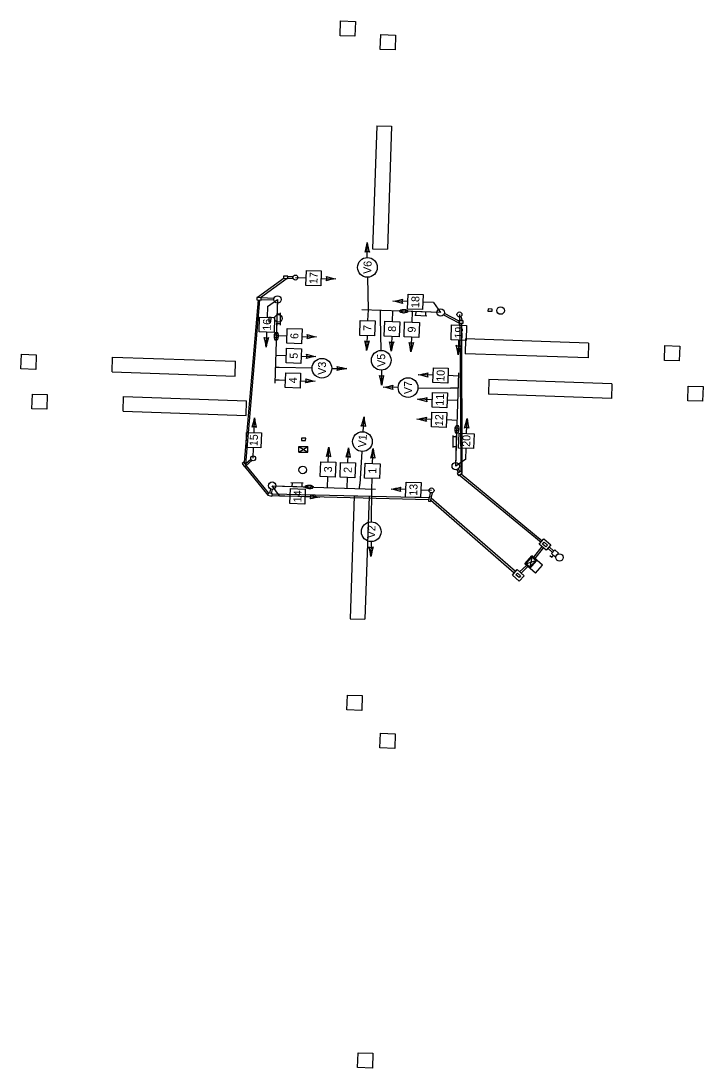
# Model space of a CAD drawing. Extents: x 981632 to 1295361, y 220574 to 1844132.
# Drawn here: x 992357 to 992633.9, y 1843107.7 to 1843532.8 of the extents above; entities that cross this region are included whole.
import ezdxf

# ---------------------------------------------------------------- set-up
doc = ezdxf.new("R2010")
doc.units = 0
for name, color, linetype in [('No Plot', 7, 'Continuous'), ('R_Existing Signal', 7, 'Continuous'), ('T_Drafting', 7, 'Continuous'), ('T_Indications', 7, 'Continuous'), ('V-SIGNAL-CONDUIT', 7, 'Continuous'), ('V-SIGNAL-HEAD', 7, 'Continuous'), ('V-SIGNAL-HEAD-MOT', 7, 'Continuous'), ('V-SIGNAL-LOOP', 7, 'Continuous'), ('V-SIGNAL-MAST', 7, 'Continuous'), ('V-SIGNAL-POLE', 7, 'Continuous')]:
    doc.layers.add(name, color=color, linetype=linetype)

msp = doc.modelspace()

# ---------------------------------------------------------------- linework, layer by layer
at = {"layer": 'No Plot'}
msp.add_line((992460.31, 1843387.1), (992461.89, 1843387.05), dxfattribs=at)
at = {"layer": 'R_Existing Signal'}
for p, q in [((992546.62, 1843415.9), (992546.58, 1843414.99)), ((992546.58, 1843414.99), (992548.33, 1843414.93)), ((992548.37, 1843415.84), (992546.62, 1843415.9)), ((992548.33, 1843414.93), (992548.37, 1843415.84)), ((992457.65, 1843412.39), (992457.6, 1843410.64)), ((992457.6, 1843410.64), (992458.51, 1843410.61)), ((992458.57, 1843412.36), (992457.65, 1843412.39)), ((992458.51, 1843410.61), (992458.57, 1843412.36)), ((992470.87, 1843363.44), (992470.84, 1843362.53)), ((992472.62, 1843363.38), (992470.87, 1843363.44)), ((992472.59, 1843362.47), (992472.62, 1843363.38)), ((992469.87, 1843360.05), (992473.53, 1843357.8)), ((992469.87, 1843357.8), (992473.53, 1843360.05)), ((992469.87, 1843360.05), (992473.53, 1843360.05)), ((992469.87, 1843357.8), (992469.87, 1843360.05)), ((992470.84, 1843362.53), (992472.59, 1843362.47)), ((992473.53, 1843357.8), (992473.53, 1843360.05)), ((992469.87, 1843357.8), (992473.53, 1843357.8))]:
    msp.add_line(p, q, dxfattribs=at)
for centre in [(992551.74, 1843415.25), (992461.54, 1843412.06), (992471.4, 1843350.52)]:
    msp.add_circle(centre, 1.53, dxfattribs=at)
at = {"layer": 'T_Drafting'}
for p, q in [((992573.69, 1843318.06), (992572.37, 1843316.56)), ((992572.37, 1843316.56), (992573.88, 1843315.24)), ((992573.69, 1843318.06), (992575.2, 1843316.75)), ((992575.2, 1843316.75), (992573.88, 1843315.24)), ((992561.56, 1843312.36), (992564.41, 1843315.62)), ((992565.88, 1843308.58), (992561.56, 1843312.36)), ((992562.02, 1843312.39), (992564.44, 1843315.15)), ((992563.59, 1843311.02), (992562.02, 1843312.39)), ((992562.04, 1843312.41), (992566, 1843313.78)), ((992564.44, 1843315.15), (992563.59, 1843311.02)), ((992563.59, 1843311.02), (992566, 1843313.78)), ((992563.62, 1843310.56), (992566.47, 1843313.82)), ((992568.73, 1843311.84), (992564.41, 1843315.62)), ((992566, 1843313.78), (992564.44, 1843315.15)), ((992571.72, 1843315.8), (992572.47, 1843315.15)), ((992573.13, 1843315.9), (992572.47, 1843315.15)), ((992565.88, 1843308.58), (992568.73, 1843311.84))]:
    msp.add_line(p, q, dxfattribs=at)
msp.add_circle((992575.67, 1843315.01), 1.5, dxfattribs=at)
at = {"layer": 'T_Indications'}
for p, q in [((992497.62, 1843436.78), (992497.54, 1843442.84)), ((992468.42, 1843428.65), (992472.77, 1843428.5)), ((992478.83, 1843428.31), (992484.87, 1843428.09)), ((992514.08, 1843418.89), (992508.04, 1843419.09)), ((992524.49, 1843418.53), (992520.14, 1843418.68)), ((992457.09, 1843416.84), (992456.94, 1843412.5)), ((992497.91, 1843415.48), (992497.76, 1843411.14)), ((992507.91, 1843415.14), (992507.75, 1843410.79)), ((992515.9, 1843414.86), (992515.75, 1843410.52)), ((992535.03, 1843413.66), (992534.88, 1843409.32)), ((992456.74, 1843406.44), (992456.53, 1843400.4)), ((992460.67, 1843405.1), (992465.02, 1843404.96)), ((992471.01, 1843404.76), (992477.05, 1843404.56)), ((992497.57, 1843405.07), (992497.35, 1843399.04)), ((992507.56, 1843404.73), (992507.35, 1843398.7)), ((992515.56, 1843404.46), (992515.34, 1843398.42)), ((992534.69, 1843403.26), (992534.47, 1843397.22)), ((992460.41, 1843397.11), (992464.75, 1843396.96)), ((992470.75, 1843396.77), (992476.79, 1843396.57)), ((992483.19, 1843391.76), (992489.26, 1843391.67)), ((992503.35, 1843391.05), (992503.45, 1843384.99)), ((992524.37, 1843389), (992518.34, 1843389.2)), ((992534.71, 1843388.66), (992530.37, 1843388.81)), ((992460.08, 1843387.11), (992464.43, 1843386.97)), ((992470.42, 1843386.77), (992476.46, 1843386.57)), ((992510.16, 1843384.04), (992504.1, 1843384.14)), ((992524.04, 1843379.01), (992518.01, 1843379.21)), ((992534.39, 1843378.67), (992530.04, 1843378.81)), ((992451.62, 1843365.65), (992451.84, 1843371.69)), ((992495.9, 1843366.02), (992496.29, 1843372.08)), ((992523.78, 1843371.01), (992517.74, 1843371.21)), ((992534.12, 1843370.67), (992529.78, 1843370.82)), ((992537.91, 1843365.36), (992538.11, 1843371.4)), ((992451.27, 1843355.25), (992451.43, 1843359.59)), ((992481.78, 1843353.78), (992481.99, 1843359.81)), ((992489.77, 1843353.5), (992489.99, 1843359.54)), ((992499.77, 1843353.16), (992499.98, 1843359.2)), ((992537.57, 1843354.95), (992537.72, 1843359.3)), ((992481.43, 1843343.37), (992481.59, 1843347.72)), ((992489.43, 1843343.1), (992489.58, 1843347.44)), ((992499.42, 1843342.76), (992499.58, 1843347.1)), ((992513.3, 1843342.55), (992507.27, 1843342.77)), ((992523.71, 1843342.2), (992519.36, 1843342.36)), ((992461.92, 1843340.08), (992466.27, 1843339.91)), ((992472.33, 1843339.7), (992478.36, 1843339.47)), ((992499.17, 1843321.45), (992499.1, 1843315.39))]:
    msp.add_line(p, q, dxfattribs=at)
for points in [[(992472.66, 1843425.48), (992472.88, 1843431.54), (992478.94, 1843431.33), (992478.72, 1843425.27)], [(992520.24, 1843421.71), (992520.04, 1843415.65), (992513.98, 1843415.85), (992514.18, 1843421.92)], [(992453.92, 1843412.6), (992459.98, 1843412.39), (992459.77, 1843406.33), (992453.71, 1843406.55)], [(992494.74, 1843411.24), (992500.81, 1843411.03), (992500.59, 1843404.97), (992494.53, 1843405.18)], [(992504.74, 1843410.9), (992510.8, 1843410.68), (992510.58, 1843404.63), (992504.52, 1843404.84)], [(992512.73, 1843410.62), (992518.79, 1843410.41), (992518.58, 1843404.35), (992512.52, 1843404.57)], [(992464.92, 1843401.96), (992465.11, 1843407.96), (992471.11, 1843407.76), (992470.91, 1843401.76)], [(992531.86, 1843409.43), (992537.92, 1843409.21), (992537.71, 1843403.15), (992531.65, 1843403.37)], [(992464.66, 1843393.97), (992464.85, 1843399.96), (992470.85, 1843399.76), (992470.65, 1843393.77)], [(992464.33, 1843383.97), (992464.52, 1843389.97), (992470.52, 1843389.77), (992470.32, 1843383.77)], [(992530.47, 1843391.8), (992530.27, 1843385.81), (992524.27, 1843386), (992524.47, 1843392)], [(992530.14, 1843381.81), (992529.94, 1843375.81), (992523.95, 1843376.01), (992524.14, 1843382.01)], [(992529.88, 1843373.81), (992529.68, 1843367.82), (992523.68, 1843368.01), (992523.88, 1843374.01)], [(992454.44, 1843359.48), (992448.38, 1843359.7), (992448.6, 1843365.76), (992454.66, 1843365.54)], [(992540.74, 1843359.19), (992534.68, 1843359.4), (992534.88, 1843365.46), (992540.94, 1843365.25)], [(992484.6, 1843347.61), (992478.54, 1843347.82), (992478.75, 1843353.88), (992484.82, 1843353.67)], [(992492.6, 1843347.34), (992486.54, 1843347.55), (992486.75, 1843353.61), (992492.81, 1843353.4)], [(992502.59, 1843346.99), (992496.53, 1843347.21), (992496.74, 1843353.27), (992502.8, 1843353.05)], [(992466.15, 1843336.9), (992466.38, 1843342.96), (992472.44, 1843342.72), (992472.21, 1843336.66)], [(992519.47, 1843345.37), (992519.25, 1843339.31), (992513.19, 1843339.53), (992513.41, 1843345.59)]]:
    msp.add_lwpolyline(points, close=True, dxfattribs=at)
for centre in [(992497.68, 1843432.78), (992503.28, 1843395.05), (992479.19, 1843391.82), (992514.16, 1843383.98), (992495.64, 1843362.03), (992499.22, 1843325.45)]:
    msp.add_circle(centre, 4, dxfattribs=at)
for centre, radius, start, end in [((992468.34, 1843446.85), 29.47, 344.4414, 352.1795), ((992526.61, 1843447.66), 29.47, 189.3961, 197.1342), ((992497.61, 1843437.58), 1.63, 58.9405, 122.6351), ((992479.6, 1843428.28), 1.63, 326.1248, 29.8195), ((992488.24, 1843398.81), 29.47, 96.5805, 104.3186), ((992490.31, 1843457.06), 29.47, 251.6257, 259.3638), ((992504.62, 1843448.36), 29.47, 276.6738, 284.4119), ((992502.65, 1843390.11), 29.47, 71.719, 79.4571), ((992513.31, 1843418.91), 1.63, 146.2181, 209.9128), ((992456.72, 1843405.66), 1.63, 236.1145, 299.8091), ((992427.25, 1843397.03), 29.47, 6.5701, 14.3082), ((992485.49, 1843394.96), 29.47, 161.6154, 169.3535), ((992471.79, 1843404.74), 1.63, 326.2721, 29.9668), ((992480.5, 1843375.29), 29.47, 96.7278, 104.4659), ((992482.42, 1843433.54), 29.47, 251.773, 259.5111), ((992497.54, 1843404.3), 1.63, 236.1248, 299.8195), ((992468.08, 1843395.66), 29.47, 6.5805, 14.3186), ((992526.32, 1843393.6), 29.47, 161.6257, 169.3638), ((992507.53, 1843403.96), 1.63, 236.1248, 299.8195), ((992478.07, 1843395.32), 29.47, 6.5805, 14.3186), ((992536.31, 1843393.26), 29.47, 161.6257, 169.3638), ((992515.53, 1843403.68), 1.63, 236.1248, 299.8195), ((992486.07, 1843395.04), 29.47, 6.5805, 14.3186), ((992544.31, 1843392.98), 29.47, 161.6257, 169.3638), ((992471.52, 1843396.74), 1.63, 326.2721, 29.9668), ((992482.15, 1843425.55), 29.47, 251.773, 259.5111), ((992534.66, 1843402.49), 1.63, 236.1248, 299.8195), ((992505.19, 1843393.85), 29.47, 6.5805, 14.3186), ((992563.44, 1843391.78), 29.47, 161.6257, 169.3638), ((992480.24, 1843367.3), 29.47, 96.7278, 104.4659), ((992483.99, 1843391.75), 1.63, 327.2794, 30.974), ((992493.22, 1843362.46), 29.47, 97.735, 105.4731), ((992494.11, 1843420.74), 29.47, 252.7802, 260.5184), ((992503.36, 1843390.25), 1.63, 239.1324, 302.8271), ((992474.39, 1843380.08), 29.47, 9.5881, 17.3262), ((992532.66, 1843381.07), 29.47, 164.6333, 172.3714), ((992514.88, 1843418.47), 29.47, 276.7278, 284.4659), ((992512.97, 1843360.22), 29.47, 71.773, 79.5111), ((992523.6, 1843389.03), 1.63, 146.2721, 209.9668), ((992471.2, 1843386.75), 1.63, 326.2721, 29.9668), ((992479.91, 1843357.3), 29.47, 96.7278, 104.4659), ((992481.82, 1843415.55), 29.47, 251.773, 259.5111), ((992500.14, 1843413.34), 29.47, 277.719, 285.4571), ((992509.36, 1843384.06), 1.63, 147.2633, 210.958), ((992499.23, 1843355.07), 29.47, 72.7642, 80.5023), ((992514.55, 1843408.48), 29.47, 276.7278, 284.4659), ((992512.64, 1843350.23), 29.47, 71.773, 79.5111), ((992523.27, 1843379.03), 1.63, 146.2721, 209.9668), ((992422.88, 1843377.15), 29.47, 341.5803, 349.3184), ((992481.12, 1843375.04), 29.47, 186.5351, 194.2732), ((992467.5, 1843378.36), 29.47, 339.9576, 347.6957), ((992525.66, 1843374.6), 29.47, 184.9124, 192.6505), ((992514.29, 1843400.48), 29.47, 276.7278, 284.4659), ((992523.01, 1843371.04), 1.63, 146.2721, 209.9668), ((992451.65, 1843366.43), 1.63, 56.0794, 119.7741), ((992495.95, 1843366.82), 1.63, 54.4567, 118.1514), ((992512.38, 1843342.23), 29.47, 71.773, 79.5111), ((992509.14, 1843376.8), 29.47, 341.6897, 349.4278), ((992537.93, 1843366.13), 1.63, 56.1888, 119.8834), ((992567.39, 1843374.81), 29.47, 186.6444, 194.3825), ((992453.03, 1843365.25), 29.47, 341.6248, 349.3629), ((992511.27, 1843363.19), 29.47, 186.5795, 194.3176), ((992461.02, 1843364.98), 29.47, 341.6248, 349.3629), ((992519.26, 1843362.92), 29.47, 186.5795, 194.3176), ((992471.02, 1843364.64), 29.47, 341.6248, 349.3629), ((992529.26, 1843362.57), 29.47, 186.5795, 194.3176), ((992481.81, 1843354.55), 1.63, 56.1239, 119.8185), ((992489.8, 1843354.28), 1.63, 56.1239, 119.8185), ((992499.79, 1843353.93), 1.63, 56.1239, 119.8185), ((992503.91, 1843372.05), 29.47, 276.5351, 284.2732), ((992501.8, 1843313.81), 29.47, 71.5803, 79.3184), ((992512.53, 1843342.58), 1.63, 146.0794, 209.7741), ((992473.1, 1843339.67), 1.63, 325.9651, 29.6598), ((992481.66, 1843310.18), 29.47, 96.4208, 104.1589), ((992483.88, 1843368.42), 29.47, 251.466, 259.2041), ((992469.91, 1843311.32), 29.47, 7.9412, 15.6793), ((992499.16, 1843320.66), 1.63, 237.4856, 301.1802), ((992528.19, 1843310.64), 29.47, 162.9865, 170.7246)]:
    msp.add_arc(centre, radius, start, end, dxfattribs=at)
at = {"layer": 'V-SIGNAL-CONDUIT'}
for p, q in [((992463.82, 1843428.35), (992453.05, 1843420.5)), ((992465.02, 1843428.31), (992454.25, 1843420.46)), ((992463.58, 1843429.27), (992463.55, 1843428.36)), ((992463.55, 1843428.36), (992465.3, 1843428.3)), ((992465.33, 1843429.21), (992463.58, 1843429.27)), ((992465.3, 1843428.3), (992465.33, 1843429.21)), ((992465.3, 1843428.38), (992467.48, 1843428.31)), ((992465.33, 1843429.12), (992467.51, 1843429.05)), ((992453.32, 1843419.57), (992447.58, 1843353.66)), ((992453.92, 1843419.55), (992448.11, 1843352.9)), ((992452.77, 1843420.51), (992452.74, 1843419.59)), ((992452.74, 1843419.59), (992454.49, 1843419.53)), ((992454.52, 1843420.45), (992452.77, 1843420.51)), ((992454.49, 1843419.53), (992454.52, 1843420.45)), ((992459.69, 1843419.44), (992454.49, 1843419.62)), ((992459.71, 1843420.18), (992454.52, 1843420.36)), ((992528.86, 1843414.13), (992534.82, 1843411.04)), ((992528.52, 1843413.47), (992534.79, 1843410.22)), ((992534.82, 1843411.09), (992534.79, 1843410.17)), ((992534.79, 1843410.17), (992536.54, 1843410.11)), ((992536.57, 1843411.03), (992534.82, 1843411.09)), ((992534.9, 1843412.67), (992535.31, 1843411.07)), ((992535.66, 1843349.97), (992535.29, 1843410.16)), ((992535.62, 1843412.85), (992536.08, 1843411.05)), ((992536.11, 1843349.17), (992536.03, 1843410.13)), ((992536.54, 1843410.11), (992536.57, 1843411.03)), ((992450.36, 1843354.83), (992448.15, 1843352.84)), ((992447.55, 1843353.7), (992446.8, 1843353.18)), ((992446.8, 1843353.18), (992447.8, 1843351.74)), ((992448.55, 1843352.27), (992447.55, 1843353.7)), ((992447.8, 1843351.74), (992448.55, 1843352.27)), ((992447.87, 1843351.79), (992457.17, 1843340.31)), ((992448.48, 1843352.22), (992457.39, 1843341.2)), ((992450.76, 1843354.38), (992448.5, 1843352.35)), ((992533.9, 1843350.59), (992534.58, 1843349.37)), ((992534.54, 1843350.95), (992535.22, 1843349.73)), ((992535.66, 1843349.97), (992534.13, 1843349.12)), ((992534.13, 1843349.12), (992534.58, 1843348.32)), ((992534.58, 1843348.32), (992536.11, 1843349.17)), ((992534.98, 1843348.54), (992568.14, 1843321.21)), ((992536.11, 1843349.17), (992535.66, 1843349.97)), ((992535.68, 1843348.93), (992568.63, 1843321.77)), ((992458.31, 1843342.82), (992457.88, 1843341.08)), ((992459.03, 1843342.64), (992458.6, 1843340.91)), ((992457.39, 1843341.2), (992457.17, 1843340.31)), ((992457.17, 1843340.31), (992458.87, 1843339.89)), ((992459.09, 1843340.78), (992457.39, 1843341.2)), ((992458.87, 1843339.89), (992459.09, 1843340.78)), ((992522.53, 1843338.44), (992458.89, 1843339.97)), ((992522.67, 1843339.17), (992459.07, 1843340.71)), ((992522.75, 1843339.6), (992522.42, 1843337.88)), ((992522.42, 1843337.88), (992523.32, 1843337.71)), ((992523.65, 1843339.43), (992522.75, 1843339.6)), ((992523.17, 1843341.36), (992522.83, 1843339.58)), ((992523.32, 1843337.71), (992523.65, 1843339.43)), ((992557.23, 1843308.68), (992523.41, 1843338.18)), ((992523.9, 1843341.22), (992523.56, 1843339.44)), ((992557.72, 1843309.23), (992523.57, 1843339.02)), ((992567.4, 1843320.36), (992569.32, 1843322.55)), ((992568.81, 1843320.45), (992569.41, 1843321.14)), ((992569.32, 1843322.55), (992572.14, 1843320.08)), ((992569.41, 1843321.14), (992570.73, 1843319.99)), ((992568.51, 1843319.38), (992565.03, 1843315.07)), ((992569.07, 1843318.89), (992565.59, 1843314.59)), ((992570.22, 1843317.89), (992567.4, 1843320.36)), ((992570.12, 1843319.3), (992568.81, 1843320.45)), ((992570.73, 1843319.99), (992570.12, 1843319.3)), ((992572.14, 1843320.08), (992570.22, 1843317.89)), ((992572.8, 1843317.05), (992570.94, 1843318.71)), ((992573.29, 1843317.6), (992571.42, 1843319.27)), ((992556.51, 1843307.85), (992558.43, 1843310.05)), ((992559.34, 1843305.38), (992556.51, 1843307.85)), ((992557.92, 1843307.95), (992558.53, 1843308.64)), ((992559.24, 1843306.79), (992557.92, 1843307.95)), ((992558.43, 1843310.05), (992561.26, 1843307.58)), ((992558.53, 1843308.64), (992559.84, 1843307.48)), ((992562.22, 1843311.78), (992559.46, 1843309.15)), ((992562.78, 1843311.29), (992560.02, 1843308.66)), ((992559.84, 1843307.48), (992559.24, 1843306.79)), ((992561.26, 1843307.58), (992559.34, 1843305.38))]:
    msp.add_line(p, q, dxfattribs=at)
at = {"layer": 'V-SIGNAL-HEAD'}
for p, q in [((992461.15, 1843419.76), (992460.66, 1843404.77)), ((992527.4, 1843414.47), (992512.41, 1843414.98)), ((992533.51, 1843352.04), (992534, 1843367.02)), ((992459.01, 1843344.14), (992474, 1843343.63))]:
    msp.add_line(p, q, dxfattribs=at)
for centre in [(992512.41, 1843414.98), (992460.66, 1843404.77), (992534.01, 1843367.02), (992474, 1843343.63)]:
    msp.add_circle(centre, 0.75, dxfattribs=at)
for centre, major_axis in [((992512.41, 1843414.98), (1.7, -0.06)), ((992460.66, 1843404.77), (0.06, 1.7)), ((992534.01, 1843367.02), (-0.06, -1.7)), ((992474, 1843343.63), (-1.7, 0.06))]:
    msp.add_ellipse(centre, major_axis=major_axis, ratio=0.441176, dxfattribs=at)
at = {"layer": 'V-SIGNAL-LOOP'}
for p, q in [((992486.59, 1843526.84), (992486.8, 1843532.84)), ((992486.8, 1843532.84), (992492.79, 1843532.63)), ((992492.79, 1843532.63), (992492.59, 1843526.64)), ((992492.59, 1843526.64), (992486.59, 1843526.84)), ((992502.88, 1843521.28), (992503.09, 1843527.28)), ((992503.09, 1843527.28), (992509.09, 1843527.07)), ((992509.09, 1843527.07), (992508.88, 1843521.07)), ((992508.88, 1843521.07), (992502.88, 1843521.28)), ((992501.48, 1843490.31), (992499.77, 1843440.34)), ((992501.48, 1843490.31), (992507.48, 1843490.1)), ((992507.48, 1843490.1), (992505.76, 1843440.13)), ((992499.77, 1843440.34), (992505.76, 1843440.13)), ((992537.51, 1843403.74), (992537.3, 1843397.74)), ((992587.48, 1843402.03), (992537.51, 1843403.74)), ((992587.48, 1843402.03), (992587.28, 1843396.03)), ((992357, 1843391.53), (992357.21, 1843397.53)), ((992357.21, 1843397.53), (992363.21, 1843397.32)), ((992363.21, 1843397.32), (992363, 1843391.33)), ((992587.28, 1843396.03), (992537.3, 1843397.74)), ((992618.26, 1843395), (992618.46, 1843401)), ((992618.46, 1843401), (992624.46, 1843400.79)), ((992624.46, 1843400.79), (992624.25, 1843394.79)), ((992393.99, 1843390.36), (992394.19, 1843396.36)), ((992394.19, 1843396.36), (992444.16, 1843394.64)), ((992443.96, 1843388.65), (992444.16, 1843394.64)), ((992624.25, 1843394.79), (992618.26, 1843395)), ((992363, 1843391.33), (992357, 1843391.53)), ((992393.99, 1843390.36), (992443.96, 1843388.65)), ((992546.97, 1843387.25), (992546.77, 1843381.25)), ((992596.94, 1843385.53), (992546.97, 1843387.25)), ((992596.94, 1843385.53), (992596.74, 1843379.54)), ((992627.73, 1843378.6), (992627.93, 1843384.6)), ((992627.93, 1843384.6), (992633.93, 1843384.39)), ((992633.93, 1843384.39), (992633.72, 1843378.39)), ((992361.47, 1843375.34), (992361.68, 1843381.34)), ((992361.68, 1843381.34), (992367.68, 1843381.13)), ((992367.68, 1843381.13), (992367.47, 1843375.14)), ((992398.46, 1843374.34), (992398.67, 1843380.33)), ((992398.67, 1843380.33), (992448.64, 1843378.62)), ((992596.74, 1843379.54), (992546.77, 1843381.25)), ((992448.43, 1843372.62), (992448.64, 1843378.62)), ((992633.72, 1843378.39), (992627.73, 1843378.6)), ((992367.47, 1843375.14), (992361.47, 1843375.34)), ((992398.46, 1843374.34), (992448.43, 1843372.62)), ((992492.33, 1843340.06), (992490.61, 1843290.09)), ((992492.33, 1843340.06), (992498.32, 1843339.86)), ((992498.32, 1843339.86), (992496.61, 1843289.89)), ((992490.61, 1843290.09), (992496.61, 1843289.89)), ((992489.34, 1843253.11), (992489.55, 1843259.11)), ((992489.55, 1843259.11), (992495.55, 1843258.9)), ((992495.55, 1843258.9), (992495.34, 1843252.91)), ((992495.34, 1843252.91), (992489.34, 1843253.11)), ((992502.77, 1843237.64), (992502.97, 1843243.64)), ((992502.97, 1843243.64), (992508.97, 1843243.44)), ((992508.97, 1843243.44), (992508.76, 1843237.44)), ((992508.76, 1843237.44), (992502.77, 1843237.64)), ((992493.69, 1843107.88), (992493.89, 1843113.88)), ((992493.89, 1843113.88), (992499.89, 1843113.67)), ((992499.89, 1843113.67), (992499.68, 1843107.67)), ((992499.68, 1843107.67), (992493.69, 1843107.88))]:
    msp.add_line(p, q, dxfattribs=at)
at = {"layer": 'V-SIGNAL-MAST'}
for p, q in [((992462.34, 1843409.33), (992462.42, 1843414.32)), ((992517.35, 1843413.34), (992517.41, 1843414.8)), ((992521.35, 1843413.18), (992521.41, 1843414.63)), ((992462.35, 1843409.83), (992460.89, 1843409.85)), ((992462.41, 1843413.82), (992460.96, 1843413.85)), ((992516.85, 1843413.37), (992521.85, 1843413.15)), ((992532.4, 1843364.58), (992532.31, 1843359.58)), ((992532.39, 1843364.08), (992533.84, 1843364.06)), ((992532.32, 1843360.08), (992533.77, 1843360.06)), ((992471.58, 1843345.16), (992466.58, 1843345.33)), ((992467.08, 1843345.32), (992467.03, 1843343.87)), ((992471.08, 1843345.18), (992471.03, 1843343.73))]:
    msp.add_line(p, q, dxfattribs=at)
at = {"layer": 'V-SIGNAL-POLE'}
for p, q in [((992497.73, 1843428.78), (992497.91, 1843415.48)), ((992457.09, 1843416.84), (992461.15, 1843419.76)), ((992461.15, 1843419.76), (992460.04, 1843385.78)), ((992524.49, 1843418.53), (992527.4, 1843414.47)), ((992527.4, 1843414.47), (992495.41, 1843415.56)), ((992502.98, 1843412.35), (992502.93, 1843415.31)), ((992503.21, 1843399.05), (992502.98, 1843412.35)), ((992461.89, 1843392.09), (992460.24, 1843392.11)), ((992475.19, 1843391.88), (992461.89, 1843392.09)), ((992533.51, 1843352.04), (992534.76, 1843390.02)), ((992518.16, 1843383.92), (992531.46, 1843383.71)), ((992534.55, 1843383.67), (992531.46, 1843383.71)), ((992495.38, 1843358.04), (992494.53, 1843344.77)), ((992537.57, 1843354.95), (992533.51, 1843352.04)), ((992459.01, 1843344.14), (992500.99, 1843342.7)), ((992461.92, 1843340.08), (992459.01, 1843344.14)), ((992494.41, 1843342.93), (992494.53, 1843344.77)), ((992499.27, 1843329.45), (992499.42, 1843342.76))]:
    msp.add_line(p, q, dxfattribs=at)
for centre, radius in [((992468.42, 1843428.65), 1), ((992461.15, 1843419.76), 1.5), ((992527.4, 1843414.47), 1.5), ((992535.03, 1843413.66), 1), ((992451.27, 1843355.24), 1), ((992533.51, 1843352.04), 1.5), ((992459.01, 1843344.14), 1.5), ((992523.71, 1843342.2), 1)]:
    msp.add_circle(centre, radius, dxfattribs=at)

# ---------------------------------------------------------------- texts
at = {"layer": 'V-SIGNAL-HEAD-MOT'}
for s, rotation, p in [('V6', 87.5733, (992499.19, 1843430.04)), ('17', 88.0361, (992477.34, 1843425.93)), ('18', 88.0361, (992518.65, 1843416.25)), ('16', 88.0361, (992458.39, 1843406.99)), ('6', 88.0361, (992469.6, 1843403.65)), ('7', 88.0361, (992499.25, 1843406.89)), ('8', 88.0361, (992509.25, 1843406.55)), ('9', 88.0361, (992517.24, 1843406.27)), ('19', 88.0361, (992536.33, 1843403.81)), ('5', 88.0361, (992469.34, 1843395.64)), ('V5', 90.9969, (992504.95, 1843392.39)), ('V3', 89.1494, (992480.78, 1843389.13)), ('10', 88.0361, (992528.91, 1843386.27)), ('4', 88.0361, (992469.01, 1843385.66)), ('V7', 89.1091, (992515.74, 1843381.28)), ('11', 88.0361, (992528.59, 1843376.58)), ('12', 88.0361, (992528.32, 1843368.26)), ('15', 88.0361, (992453.06, 1843360.13)), ('V1', 86.245, (992497.11, 1843359.57)), ('20', 88.0361, (992539.35, 1843359.86)), ('3', 88.0361, (992483.26, 1843349.53)), ('2', 88.0361, (992491.26, 1843349.28)), ('1', 88.0361, (992501.25, 1843348.96)), ('14', 88.0361, (992470.84, 1843337.34)), ('13', 88.0361, (992517.87, 1843339.98)), ('V2', 87.5514, (992500.73, 1843322.73))]:
    msp.add_text(s, height=3.25, rotation=rotation, dxfattribs=at).set_placement(p)

doc.saveas('drawing.dxf')
